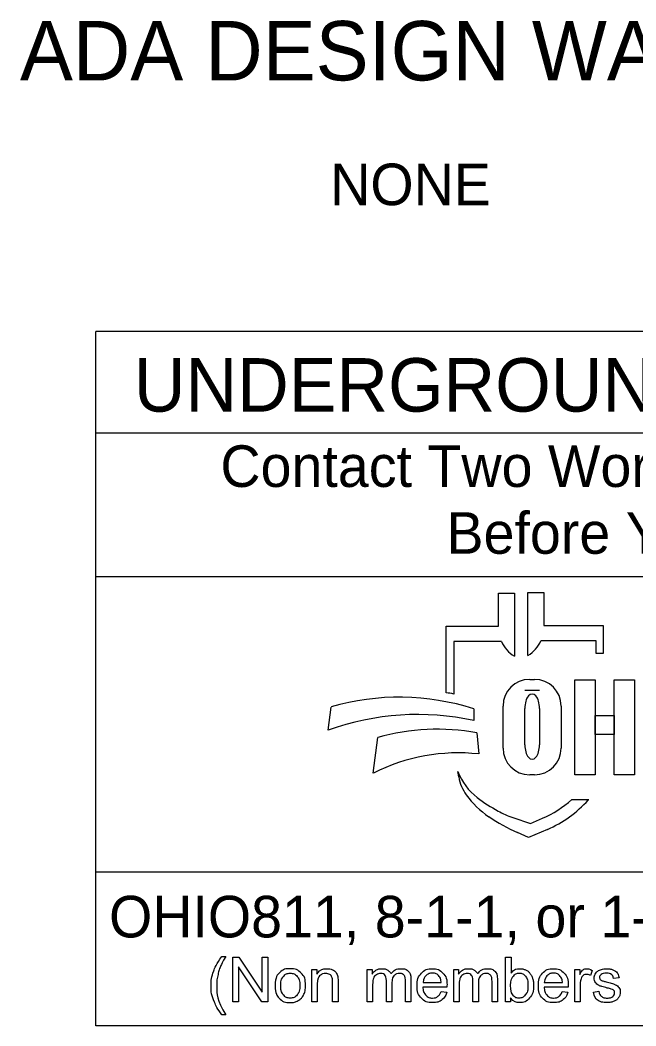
# Model space of a CAD drawing. Extents: x -17.5 to 72.9, y -57.8 to 32.3.
# Drawn here: x 1.995 to 4.069, y 2.143 to 5.529 of the extents above; entities that cross this region are included whole.
import ezdxf

# ---------------------------------------------------------------- set-up
doc = ezdxf.new("R2010")
doc.units = 0
doc.layers.add('SH_Data', color=7, linetype='Continuous')
doc.layers.add('SH_Text', color=7, linetype='Continuous')

msp = doc.modelspace()

# ---------------------------------------------------------------- linework, layer by layer
at = {"layer": 'SH_Data'}
for p, q in [((2.2499, 2.1428), (2.2499, 4.4803)), ((6.4999, 4.4803), (2.2499, 4.4803)), ((2.2499, 4.1387), (6.4999, 4.1387)), ((2.2499, 3.6553), (6.4999, 3.6553)), ((6.4999, 2.6607), (2.2499, 2.6607)), ((6.4999, 2.1428), (2.2499, 2.1428))]:
    msp.add_line(p, q, dxfattribs=at)
at = {"layer": 'SH_Text'}
for p, q in [((3.6059, 3.4883), (3.6059, 3.5998)), ((3.6059, 3.5998), (3.6596, 3.5998)), ((3.6596, 3.5998), (3.6596, 3.3877)), ((3.7052, 3.39), (3.7052, 3.6021)), ((3.7052, 3.6021), (3.7589, 3.6021)), ((3.7589, 3.6021), (3.7589, 3.4906)), ((3.43, 3.2644), (3.43, 3.4883)), ((3.43, 3.4883), (3.6059, 3.4883)), ((3.7589, 3.4906), (3.9581, 3.4906)), ((3.9581, 3.4906), (3.9581, 3.3968)), ((3.4552, 3.4369), (3.4552, 3.26)), ((3.6163, 3.4369), (3.4552, 3.4369)), ((3.9348, 3.4392), (3.7485, 3.4392)), ((3.9348, 3.3968), (3.9348, 3.4392)), ((3.9581, 3.3968), (3.9348, 3.3968)), ((3.7109, 3.3091), (3.7275, 3.3091)), ((3.7442, 3.2721), (3.6944, 3.2721)), ((3.6215, 3.0776), (3.6215, 3.2196)), ((3.8169, 3.2196), (3.8169, 3.0776)), ((3.0326, 3.1381), (3.042, 3.2162)), ((3.5233, 3.2097), (3.5233, 3.1709)), ((3.6944, 3.089), (3.6944, 3.2114)), ((3.7442, 3.2114), (3.7442, 3.089)), ((3.5332, 3.1291), (3.5395, 3.0582)), ((3.1844, 2.9936), (3.1991, 3.1137)), ((3.4721, 2.9807), (3.4691, 2.9986)), ((3.7275, 2.9882), (3.7109, 2.9882)), ((3.8524, 2.9048), (3.9098, 2.9048)), ((3.654, 2.8444), (3.7134, 2.8239)), ((3.7134, 2.8239), (3.7544, 2.8417)), ((3.7074, 2.7769), (3.67, 2.7934)), ((3.7707, 2.8044), (3.7074, 2.7769))]:
    msp.add_line(p, q, dxfattribs=at)
for points in [[(3.8634, 3.3081), (3.9313, 3.3081), (3.9313, 2.9881), (3.8634, 2.9881)], [(3.9955, 3.3081), (4.0635, 3.3081), (4.0635, 2.9881), (3.9955, 2.9881)], [(3.9313, 3.1882), (3.9955, 3.1882), (3.9955, 3.1242), (3.9313, 3.1242)]]:
    msp.add_lwpolyline(points, close=True, dxfattribs=at)
for points in [[(2.6745, 2.3766), (2.6877, 2.3766)], [(2.7113, 2.2239), (2.7113, 2.3741), (2.7316, 2.3741), (2.8106, 2.2561), (2.8106, 2.3741), (2.8296, 2.3741), (2.8296, 2.2239), (2.8093, 2.2239), (2.7303, 2.3419), (2.7303, 2.2239), (2.7113, 2.2239)], [(3.6467, 2.2239), (3.6297, 2.2239), (3.6297, 2.3741), (3.6481, 2.3741), (3.6481, 2.3206)], [(2.9772, 2.2239), (2.9772, 2.3328), (2.9938, 2.3328), (2.9938, 2.3173)], [(3.1636, 2.2239), (3.1636, 2.3328), (3.1801, 2.3328), (3.1801, 2.3174)], [(3.455, 2.2239), (3.455, 2.3328), (3.4715, 2.3328), (3.4715, 2.3174)], [(3.8628, 2.2239), (3.8628, 2.3328), (3.8794, 2.3328), (3.8794, 2.3163)], [(3.9218, 2.3293), (3.9154, 2.3122)], [(4.0118, 2.3046), (3.9937, 2.3022)], [(2.9956, 2.2833), (2.9956, 2.2239), (2.9772, 2.2239)], [(3.0656, 2.2908), (3.0656, 2.2239), (3.0471, 2.2239), (3.0471, 2.2901)], [(3.1821, 2.2803), (3.1821, 2.2239), (3.1636, 2.2239)], [(3.2467, 2.2871), (3.2467, 2.2239), (3.2283, 2.2239), (3.2283, 2.2946)], [(3.3111, 2.2986), (3.3111, 2.2239), (3.2927, 2.2239), (3.2927, 2.2924)], [(3.4324, 2.2736), (3.3512, 2.2736)], [(3.3523, 2.2887), (3.413, 2.2887)], [(3.4734, 2.2803), (3.4734, 2.2239), (3.455, 2.2239)], [(3.5381, 2.2871), (3.5381, 2.2239), (3.5197, 2.2239), (3.5197, 2.2946)], [(3.6025, 2.2986), (3.6025, 2.2239), (3.5841, 2.2239), (3.5841, 2.2924)], [(3.8404, 2.2736), (3.7592, 2.2736)], [(3.7602, 2.2887), (3.821, 2.2887)], [(3.8812, 2.2809), (3.8812, 2.2239), (3.8628, 2.2239)], [(3.4128, 2.2591), (3.4319, 2.2567)], [(3.6467, 2.2375), (3.6467, 2.2239)], [(3.8208, 2.2591), (3.8399, 2.2567)], [(3.9254, 2.2564), (3.9436, 2.2593)], [(2.6877, 2.1798), (2.6745, 2.1798)]]:
    msp.add_lwpolyline(points, dxfattribs=at)
for centre, radius, start, end in [((3.7077, 3.4736), 0.0985, 201.9296, 240.7469), ((3.6571, 3.476), 0.0985, 299.2531, 338.0704), ((3.7109, 3.2196), 0.0895, 90, 180), ((3.7275, 3.2196), 0.0895, 0, 90), ((3.3018, 2.4554), 0.8191, 79.2074, 81.0007), ((3.2721, 2.4302), 0.8191, 72.1402, 106.3144), ((3.3351, 2.2991), 0.8919, 77.8238, 109.8274), ((3.399, 2.4094), 0.7322, 79.44, 105.8467), ((3.4711, 2.4262), 0.6357, 83.8248, 116.8021), ((3.7109, 3.0776), 0.0895, 180, 270), ((3.7275, 3.0776), 0.0895, 270, 0), ((3.6565, 3.0707), 0.2008, 201.0457, 232.5314), ((3.6134, 3.0048), 0.1433, 189.6817, 216.0884), ((3.7471, 3.1022), 0.3088, 216.0884, 235.7167), ((3.849, 3.3219), 0.5173, 232.5314, 241.794), ((3.611, 3.1722), 0.3602, 293.4582, 312.0712), ((3.611, 3.1722), 0.401, 293.4582, 317.8286), ((3.9136, 3.3465), 0.6044, 235.7167, 246.2325), ((3.7638, 3.1631), 0.3371, 241.794, 250.9821)]:
    msp.add_arc(centre, radius, start, end, dxfattribs=at)
for centre, start_param, end_param in [((3.7193, 3.2114), 4.712389, 7.853982), ((3.7193, 3.089), 1.570796, 4.712389)]:
    msp.add_ellipse(centre, major_axis=(0, 0.0484), ratio=0.514403, start_param=start_param, end_param=end_param, dxfattribs=at)
for points in [[(2.6745, 2.1798), (2.6592, 2.199), (2.6487, 2.2248), (2.6381, 2.2506), (2.6381, 2.2783), (2.6381, 2.3026), (2.646, 2.325), (2.6552, 2.3509), (2.6745, 2.3766)], [(2.6877, 2.3766), (2.6753, 2.3553), (2.6713, 2.3462), (2.6651, 2.332), (2.6615, 2.3167), (2.6571, 2.2975), (2.6571, 2.2782), (2.6571, 2.2289), (2.6877, 2.1798)], [(2.8537, 2.2783), (2.8537, 2.3085), (2.8705, 2.3231), (2.8846, 2.3352), (2.9047, 2.3352), (2.9271, 2.3352), (2.9414, 2.3205), (2.9556, 2.3058), (2.9556, 2.2799), (2.9556, 2.2589), (2.9493, 2.2469), (2.943, 2.2348), (2.931, 2.2282), (2.9189, 2.2215), (2.9047, 2.2215), (2.8819, 2.2215), (2.8678, 2.2362), (2.8537, 2.2508), (2.8537, 2.2783)], [(2.8727, 2.2783), (2.8727, 2.2574), (2.8818, 2.247), (2.8909, 2.2366), (2.9047, 2.2366), (2.9184, 2.2366), (2.9275, 2.2471), (2.9366, 2.2575), (2.9366, 2.279), (2.9366, 2.2991), (2.9275, 2.3095), (2.9183, 2.3199), (2.9047, 2.3199), (2.8909, 2.3199), (2.8818, 2.3096), (2.8727, 2.2992), (2.8727, 2.2783)], [(2.9938, 2.3173), (3.0058, 2.3352), (3.0284, 2.3352), (3.0382, 2.3352), (3.0465, 2.3316), (3.0547, 2.3281), (3.0588, 2.3224), (3.0629, 2.3166), (3.0646, 2.3087), (3.0656, 2.3036), (3.0656, 2.2908)], [(3.0471, 2.2901), (3.0471, 2.3013), (3.045, 2.3069), (3.0428, 2.3125), (3.0374, 2.3158), (3.0319, 2.3191), (3.0245, 2.3191), (3.0127, 2.3191), (3.0042, 2.3117), (2.9956, 2.3042), (2.9956, 2.2833)], [(3.1801, 2.3174), (3.1852, 2.3254), (3.1937, 2.3303), (3.2022, 2.3352), (3.2131, 2.3352), (3.2252, 2.3352), (3.2329, 2.3301), (3.2407, 2.3251), (3.2439, 2.3161), (3.2568, 2.3352), (3.2775, 2.3352), (3.2937, 2.3352), (3.3024, 2.3262), (3.3111, 2.3172), (3.3111, 2.2986)], [(3.2283, 2.2946), (3.2283, 2.3069), (3.2238, 2.313), (3.2193, 2.3191), (3.209, 2.3191), (3.2012, 2.3191), (3.1946, 2.315), (3.188, 2.311), (3.185, 2.3031), (3.1821, 2.2952), (3.1821, 2.2803)], [(3.2927, 2.2924), (3.2927, 2.3035), (3.2909, 2.3083), (3.2891, 2.3132), (3.2844, 2.3162), (3.2797, 2.3191), (3.2734, 2.3191), (3.2619, 2.3191), (3.2543, 2.3115), (3.2467, 2.3039), (3.2467, 2.2871)], [(3.4319, 2.2567), (3.4274, 2.24), (3.4152, 2.2307), (3.403, 2.2215), (3.384, 2.2215), (3.3602, 2.2215), (3.3462, 2.2362), (3.3322, 2.2509), (3.3322, 2.2774), (3.3322, 2.3049), (3.3464, 2.32), (3.3605, 2.3352), (3.383, 2.3352), (3.4048, 2.3352), (3.4187, 2.3203), (3.4325, 2.3055), (3.4325, 2.2785), (3.4325, 2.2769), (3.4324, 2.2736)], [(3.413, 2.2887), (3.4118, 2.3025), (3.4061, 2.3094), (3.3972, 2.3201), (3.3832, 2.3201), (3.3705, 2.3201), (3.3618, 2.3115), (3.3532, 2.303), (3.3523, 2.2887)], [(3.4715, 2.3174), (3.4766, 2.3254), (3.4851, 2.3303), (3.4936, 2.3352), (3.5045, 2.3352), (3.5166, 2.3352), (3.5243, 2.3301), (3.532, 2.3251), (3.5352, 2.3161), (3.5482, 2.3352), (3.5689, 2.3352), (3.5851, 2.3352), (3.5938, 2.3262), (3.6025, 2.3172), (3.6025, 2.2986)], [(3.5197, 2.2946), (3.5197, 2.3069), (3.5152, 2.313), (3.5106, 2.3191), (3.5004, 2.3191), (3.4926, 2.3191), (3.486, 2.315), (3.4794, 2.311), (3.4764, 2.3031), (3.4734, 2.2952), (3.4734, 2.2803)], [(3.5841, 2.2924), (3.5841, 2.3035), (3.5823, 2.3083), (3.5805, 2.3132), (3.5758, 2.3162), (3.5711, 2.3191), (3.5647, 2.3191), (3.5533, 2.3191), (3.5457, 2.3115), (3.5381, 2.3039), (3.5381, 2.2871)], [(3.6465, 2.2792), (3.6465, 2.2596), (3.6518, 2.2509), (3.6605, 2.2366), (3.6753, 2.2366), (3.6874, 2.2366), (3.6962, 2.2471), (3.705, 2.2576), (3.705, 2.2784), (3.705, 2.2998), (3.6965, 2.3099), (3.6881, 2.3201), (3.6761, 2.3201), (3.6641, 2.3201), (3.6553, 2.3096), (3.6465, 2.299), (3.6465, 2.2792)], [(3.6481, 2.3206), (3.6598, 2.3352), (3.6779, 2.3352), (3.6879, 2.3352), (3.6969, 2.3311), (3.7058, 2.3271), (3.7116, 2.3198), (3.7174, 2.3124), (3.7207, 2.3021), (3.724, 2.2918), (3.724, 2.28), (3.724, 2.252), (3.7101, 2.2368), (3.6963, 2.2215), (3.6769, 2.2215), (3.6577, 2.2215), (3.6467, 2.2375)], [(3.8399, 2.2567), (3.8353, 2.24), (3.8232, 2.2307), (3.811, 2.2215), (3.792, 2.2215), (3.7682, 2.2215), (3.7542, 2.2362), (3.7402, 2.2509), (3.7402, 2.2774), (3.7402, 2.3049), (3.7544, 2.32), (3.7685, 2.3352), (3.791, 2.3352), (3.8128, 2.3352), (3.8266, 2.3203), (3.8405, 2.3055), (3.8405, 2.2785), (3.8405, 2.2769), (3.8404, 2.2736)], [(3.821, 2.2887), (3.8198, 2.3025), (3.814, 2.3094), (3.8052, 2.3201), (3.7912, 2.3201), (3.7785, 2.3201), (3.7698, 2.3115), (3.7612, 2.303), (3.7602, 2.2887)], [(3.8794, 2.3163), (3.8857, 2.3278), (3.8911, 2.3315), (3.8965, 2.3352), (3.9029, 2.3352), (3.9122, 2.3352), (3.9218, 2.3293)], [(3.9154, 2.3122), (3.9087, 2.3162), (3.9019, 2.3162), (3.8959, 2.3162), (3.8911, 2.3125), (3.8863, 2.3089), (3.8843, 2.3024), (3.8812, 2.2926), (3.8812, 2.2809)], [(3.9937, 2.3022), (3.9925, 2.3106), (3.9866, 2.3153), (3.9807, 2.3201), (3.9699, 2.3201), (3.9572, 2.3201), (3.9518, 2.3159), (3.9463, 2.3116), (3.9463, 2.306), (3.9463, 2.3024), (3.9486, 2.2995), (3.9508, 2.2966), (3.9557, 2.2946), (3.9584, 2.2936), (3.972, 2.2899), (3.9916, 2.2847), (3.9993, 2.2813), (4.0071, 2.278), (4.0115, 2.2717), (4.0159, 2.2653), (4.0159, 2.2559), (4.0159, 2.2467), (4.0105, 2.2386), (4.0051, 2.2304), (3.995, 2.226), (3.9848, 2.2215), (3.972, 2.2215), (3.9507, 2.2215), (3.9396, 2.2303), (3.9285, 2.2391), (3.9254, 2.2564)], [(3.9436, 2.2593), (3.9451, 2.2483), (3.9522, 2.2425), (3.9592, 2.2366), (3.9718, 2.2366), (3.9846, 2.2366), (3.9907, 2.2418), (3.9969, 2.247), (3.9969, 2.254), (3.9969, 2.2602), (3.9915, 2.2638), (3.9877, 2.2663), (3.9726, 2.2701), (3.9523, 2.2752), (3.9444, 2.2789), (3.9366, 2.2827), (3.9325, 2.2893), (3.9285, 2.2959), (3.9285, 2.3038), (3.9285, 2.3111), (3.9318, 2.3173), (3.9351, 2.3235), (3.9409, 2.3276), (3.9452, 2.3308), (3.9526, 2.333), (3.9601, 2.3352), (3.9686, 2.3352), (3.9814, 2.3352), (3.9911, 2.3315), (4.0008, 2.3278), (4.0054, 2.3215), (4.01, 2.3152), (4.0118, 2.3046)], [(3.3512, 2.2736), (3.3522, 2.2557), (3.3614, 2.2462), (3.3705, 2.2366), (3.3841, 2.2366), (3.3943, 2.2366), (3.4014, 2.242), (3.4086, 2.2473), (3.4128, 2.2591)], [(3.7592, 2.2736), (3.7602, 2.2557), (3.7694, 2.2462), (3.7785, 2.2366), (3.7921, 2.2366), (3.8023, 2.2366), (3.8094, 2.242), (3.8166, 2.2473), (3.8208, 2.2591)]]:
    msp.add_open_spline(points, degree=3, dxfattribs=at)

# ---------------------------------------------------------------- texts
for s, height, p in [('ADA DESIGN WAIVERS', 0.2, (1.9944, 5.3256)), ('                  NONE                 ', 0.14, (2.103, 4.9056)), ('UNDERGROUND UTILITIES', 0.18, (2.378, 4.2106)), ('Contact Two Working Days', 0.14, (2.6695, 3.9571)), ('Before You Dig', 0.14, (3.4307, 3.7321)), ('OHIO811, 8-1-1, or 1-800-362-2764', 0.14, (2.2944, 2.4406))]:
    msp.add_text(s, height=height, dxfattribs=at).set_placement(p)

doc.saveas('drawing.dxf')
